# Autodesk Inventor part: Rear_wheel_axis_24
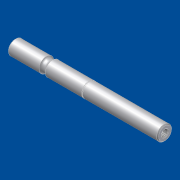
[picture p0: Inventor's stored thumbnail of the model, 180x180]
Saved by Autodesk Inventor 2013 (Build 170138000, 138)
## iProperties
Shininess: 69.0
Length Units: 11269
Angle Units: 11279
Time Units: 11290
Mass Units: 11283
Length Display Precision: 3
Angle Display Precision: 2
Created: 2001-04
Part Number: Rear_wheel_axis_24
Material: Standard
Document SubType Name: Modellieren
Designer: dl
Density: 1 g/cm^3
Density: 0.0
Volumn: 0.0
Area: 0.0
PropertySet Name: Model Information
Control State: 0
Master: False
Checked Out: False
Author: dl
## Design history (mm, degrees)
body "Solid1"
sketch "Sketch2"
  geometry: C1 r 7.5 at (0, 0) reference; 1 further point
  constraints: 1 coincident
revolve "Revolution1" stored, may be unused: angle "d8" = 90 deg
hole "Hole1" sketch "Sketch2" diameter "d9" = 6.647; stored, may be unused: countersink angle "d13" = 60 deg, drill point angle "d15" = 118 deg; dims "d10" = 20, "d11" = 4, "d12" = 2, "d14" = 23
chamfer "Chamfer1" distance "d16" = 1; stored, may be unused: second distance "d17" = 1, angle "d22" = 45 deg
chamfer "Chamfer2" distance "d18" = 0.6; stored, may be unused: second distance "d19" = 0.6, angle "d23" = 45 deg
sketch "Sketch1"
  geometry: L1 (-15.869, -1.81)-(-15.869, 5.69); L2 (-15.869, 5.69)-(15.931, 5.69); L3 (22.331, 5.69)-(59.131, 5.69); L4 (59.131, 5.69)-(59.131, 5.34); L5 (59.131, 5.34)-(60.231, 5.34); L6 (60.231, 5.34)-(60.231, 5.69); L7 (60.231, 5.69)-(136.131, 5.69); L8 (136.131, 5.69)-(136.131, -1.81); L9 (136.131, -1.81)-(-15.869, -1.81); A1 r 4 centre (19.131, 8.09) between (15.931, 5.69) and (22.331, 5.69)
  constraints: 18 end point, 4 collinear, 4 parallel, 2 perpendicular, 2 point on circle, 1 centre point, 1 vertical
  dimensions: "d0" = 7.5 distance of L1.start L1.end; "d1" = 1.1 distance of L4.end L5.end; "d2" = 7.15 vertical distance of L8.end L5.end; "d3" = 4 radius of A1; "d4" = 9.9 distance from line of L9 A1.centre; "d5" = 152 distance of L8.end L1.start; "d6" = 77 distance between parallel lines of L8 L4; "d7" = 40 distance from line of A1.centre L4
other parameters: "d21" = 0
